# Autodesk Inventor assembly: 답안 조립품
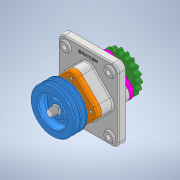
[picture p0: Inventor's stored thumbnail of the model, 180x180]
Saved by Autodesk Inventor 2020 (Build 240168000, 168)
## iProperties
Created: 2021-07
Part Number: 답안 조립품
Document SubType Name: Assembly
Designer: Owner
Author: Owner
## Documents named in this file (16)
- C:\Users\Owner\Desktop\710707V1010\답안 조립품.iam
- C:\Users\Owner\Desktop\710707V1010\본체.ipt
- C:\Users\Owner\Desktop\710707V1010\M16 너트.ipt
- C:\Users\Owner\Desktop\710707V1010\V-벨트풀리.ipt
- C:\Users\Owner\Desktop\710707V1010\멈춤나사 M4.ipt
- C:\Users\Owner\Desktop\710707V1010\베어링 6206.ipt
- C:\Users\Owner\Desktop\710707V1010\볼트 M6.ipt
- C:\Users\Owner\Desktop\710707V1010\부시.ipt
- C:\Users\Owner\Desktop\710707V1010\오일실 30x42x8.ipt
- C:\Users\Owner\Desktop\710707V1010\오일실 30x45x8.ipt
- C:\Users\Owner\Desktop\710707V1010\체인 스프로킷.ipt
- C:\Users\Owner\Desktop\710707V1010\축.ipt
- C:\Users\Owner\Desktop\710707V1010\커버A.ipt
- C:\Users\Owner\Desktop\710707V1010\키 6x6x18.ipt
- C:\Users\Owner\Desktop\710707V1010\키 6x6x20.ipt
- C:\Users\Owner\Desktop\710707V1010\커버B.ipt
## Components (3 placed, 2 different names)
1. M16 너트:1
2. V-벨트풀리:1 — 각도:1
3. M16 너트:2
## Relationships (1: Angle 1)
- 각도:1 [Angle]: V-벨트풀리:1
